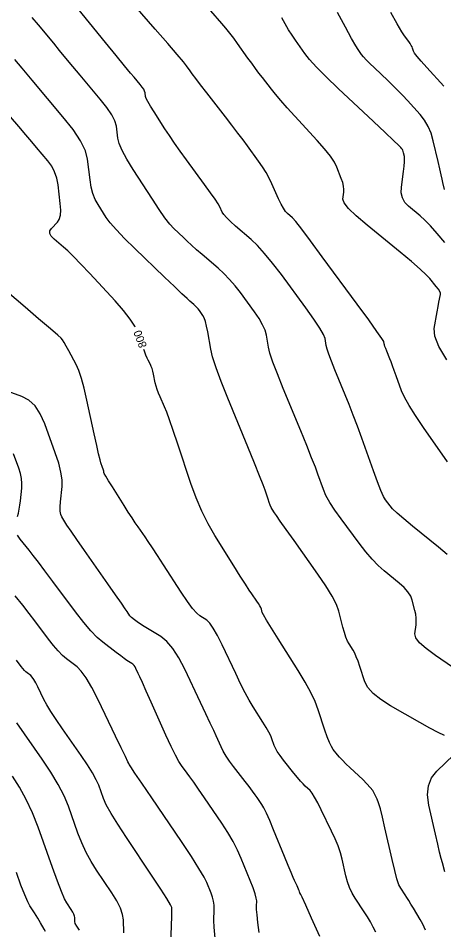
# Model space of a CAD drawing. Extents: x 2082232 to 2083549, y 592624 to 593832.
# Drawn here: x 2082448.2 to 2082485.4, y 593145.7 to 593225.4 of the extents above; entities that cross this region are included whole.
import ezdxf

# ---------------------------------------------------------------- set-up
doc = ezdxf.new("R2010")
doc.units = 0
doc.layers.add('DT_X_Contour_Major', color=7, linetype='Continuous')
doc.layers.add('DT_X_Contour_Minor', color=7, linetype='Continuous')

msp = doc.modelspace()

# ---------------------------------------------------------------- linework, layer by layer
at = {"layer": 'DT_X_Contour_Major'}
for points in [[(2082485.658, 593195.556), (2082484.97, 593196.729), (2082484.597, 593197.648), (2082484.539, 593198.314), (2082484.807, 593199.752), (2082484.898, 593200.235), (2082484.969, 593200.607), (2082485.021, 593200.868), (2082485.053, 593201.018), (2082485.113, 593201.268), (2082485.107, 593201.383), (2082485.042, 593201.539), (2082484.919, 593201.737), (2082484.738, 593201.976), (2082484.178, 593202.669), (2082483.859, 593203.008), (2082483.32, 593203.505), (2082482.563, 593204.16), (2082481.586, 593204.973), (2082478.69, 593207.352), (2082477.744, 593208.161), (2082477.076, 593208.805), (2082476.688, 593209.284), (2082476.579, 593209.597), (2082476.659, 593210.212), (2082476.668, 593210.461), (2082476.634, 593210.744), (2082476.556, 593211.064), (2082476.436, 593211.418), (2082476.056, 593212.411), (2082475.841, 593212.837), (2082475.479, 593213.367), (2082474.971, 593214.004), (2082474.316, 593214.745), (2082472.375, 593216.864), (2082471.702, 593217.607), (2082471.136, 593218.247), (2082470.678, 593218.784), (2082470.328, 593219.218), (2082469.54, 593220.237), (2082469.239, 593220.63), (2082468.928, 593221.046), (2082468.606, 593221.485), (2082468.275, 593221.946), (2082467.376, 593223.206), (2082467.036, 593223.671), (2082466.691, 593224.121), (2082466.342, 593224.556), (2082465.987, 593224.976), (2082465.033, 593226.075)], [(2082458.433, 593198.426), (2082458.396, 593198.504), (2082457.984, 593199.131), (2082457.404, 593199.867), (2082456.657, 593200.712), (2082454.443, 593203.112), (2082453.678, 593203.931), (2082453.043, 593204.59), (2082452.537, 593205.089), (2082452.162, 593205.427), (2082451.335, 593206.115), (2082451.088, 593206.367), (2082450.968, 593206.605), (2082450.973, 593206.831), (2082451.105, 593207.043), (2082451.625, 593207.591), (2082451.787, 593207.847), (2082451.882, 593208.205), (2082451.909, 593208.664), (2082451.87, 593209.224), (2082451.676, 593210.853), (2082451.566, 593211.442), (2082451.382, 593211.989), (2082451.124, 593212.492), (2082450.792, 593212.953), (2082449.808, 593214.125), (2082449.389, 593214.623), (2082448.871, 593215.238), (2082448.254, 593215.971), (2082447.537, 593216.821)], [(2082483.778, 593145.725), (2082483.551, 593146.237), (2082483.327, 593146.653), (2082482.733, 593147.639), (2082482.521, 593147.988), (2082482.329, 593148.299), (2082482.157, 593148.571), (2082482.005, 593148.803), (2082481.628, 593149.371), (2082481.475, 593149.688), (2082481.298, 593150.212), (2082481.098, 593150.943), (2082480.875, 593151.882), (2082480.249, 593154.662), (2082480.031, 593155.599), (2082479.847, 593156.327), (2082479.697, 593156.845), (2082479.581, 593157.154), (2082479.317, 593157.697), (2082479.179, 593157.924), (2082478.964, 593158.195), (2082478.671, 593158.512), (2082478.301, 593158.875), (2082477.211, 593159.902), (2082476.835, 593160.262), (2082476.525, 593160.57), (2082476.282, 593160.827), (2082476.104, 593161.033), (2082475.72, 593161.514), (2082475.566, 593161.754), (2082475.395, 593162.117), (2082475.205, 593162.6), (2082474.997, 593163.206), (2082474.417, 593164.981), (2082474.145, 593165.694), (2082473.761, 593166.502), (2082473.267, 593167.403), (2082472.662, 593168.4), (2082470.902, 593171.182), (2082470.321, 593172.109), (2082469.897, 593172.802), (2082469.632, 593173.263), (2082469.524, 593173.491), (2082469.448, 593173.787), (2082469.402, 593173.914), (2082469.322, 593174.072), (2082469.207, 593174.26), (2082469.057, 593174.48), (2082468.613, 593175.107), (2082468.389, 593175.436), (2082468.053, 593175.955), (2082467.604, 593176.663), (2082467.042, 593177.56), (2082465.392, 593180.203), (2082464.797, 593181.232), (2082464.249, 593182.335), (2082463.748, 593183.513), (2082463.294, 593184.766), (2082462.146, 593188.207), (2082461.751, 593189.378), (2082461.427, 593190.309), (2082461.173, 593191), (2082460.99, 593191.451), (2082460.597, 593192.336), (2082460.46, 593192.661), (2082460.345, 593192.974), (2082460.252, 593193.274), (2082460.181, 593193.561), (2082460.02, 593194.311), (2082459.958, 593194.574), (2082459.891, 593194.804), (2082459.822, 593194.998), (2082459.748, 593195.158), (2082459.546, 593195.539), (2082459.46, 593195.722), (2082459.352, 593195.985), (2082459.223, 593196.328), (2082459.175, 593196.463)], [(2082461.567, 593145.097), (2082461.603, 593146.311), (2082461.615, 593146.723), (2082461.622, 593147.045), (2082461.626, 593147.279), (2082461.625, 593147.425), (2082461.618, 593147.694), (2082461.51, 593147.941), (2082461.19, 593148.479), (2082460.66, 593149.308), (2082459.918, 593150.429), (2082457.658, 593153.804), (2082456.897, 593154.967), (2082456.308, 593155.922), (2082455.893, 593156.669), (2082455.65, 593157.21), (2082455.232, 593158.374), (2082455.019, 593158.865), (2082454.691, 593159.466), (2082454.25, 593160.176), (2082453.695, 593160.995), (2082452.062, 593163.324), (2082451.502, 593164.14), (2082451.045, 593164.838), (2082450.693, 593165.421), (2082450.444, 593165.886), (2082449.919, 593166.973), (2082449.732, 593167.34), (2082449.566, 593167.627), (2082449.42, 593167.835), (2082449.295, 593167.962), (2082448.987, 593168.194), (2082448.867, 593168.295), (2082448.738, 593168.425), (2082448.601, 593168.583), (2082448.455, 593168.77), (2082448.054, 593169.307)]]:
    msp.add_lwpolyline(points, dxfattribs=at)
at = {"layer": 'DT_X_Contour_Minor'}
for points in [[(2082485.711, 593186.655), (2082483.622, 593189.646), (2082482.914, 593190.688), (2082482.358, 593191.574), (2082481.955, 593192.301), (2082481.703, 593192.871), (2082481.235, 593194.181), (2082481.068, 593194.642), (2082480.92, 593195.043), (2082480.789, 593195.384), (2082480.678, 593195.664), (2082480.403, 593196.331), (2082480.312, 593196.558), (2082480.243, 593196.742), (2082480.197, 593196.88), (2082480.173, 593196.974), (2082480.141, 593197.164), (2082479.987, 593197.421), (2082479.55, 593198.051), (2082478.83, 593199.052), (2082477.827, 593200.426), (2082474.775, 593204.585), (2082473.754, 593205.967), (2082472.977, 593206.995), (2082472.446, 593207.668), (2082472.16, 593207.986), (2082471.724, 593208.361), (2082471.553, 593208.546), (2082471.369, 593208.821), (2082471.171, 593209.184), (2082470.958, 593209.636), (2082470.374, 593210.961), (2082470.137, 593211.458), (2082469.864, 593211.953), (2082469.555, 593212.448), (2082469.21, 593212.942), (2082468.243, 593214.259), (2082467.849, 593214.79), (2082467.395, 593215.393), (2082466.879, 593216.068), (2082466.303, 593216.817), (2082464.684, 593218.909), (2082464.137, 593219.617), (2082463.712, 593220.172), (2082463.409, 593220.572), (2082463.226, 593220.82), (2082462.902, 593221.274), (2082462.64, 593221.602), (2082462.099, 593222.246), (2082461.276, 593223.206), (2082460.174, 593224.481), (2082456.861, 593228.301)], [(2082485.688, 593178.55), (2082484.915, 593179.184), (2082482.666, 593181.036), (2082481.91, 593181.668), (2082481.328, 593182.175), (2082480.922, 593182.556), (2082480.69, 593182.812), (2082480.305, 593183.328), (2082480.13, 593183.631), (2082479.896, 593184.154), (2082479.602, 593184.896), (2082479.249, 593185.858), (2082478.227, 593188.716), (2082477.849, 593189.757), (2082477.482, 593190.736), (2082477.127, 593191.652), (2082476.783, 593192.507), (2082475.88, 593194.702), (2082475.578, 593195.452), (2082475.352, 593196.055), (2082475.199, 593196.51), (2082475.122, 593196.819), (2082475.015, 593197.445), (2082474.879, 593197.787), (2082474.554, 593198.343), (2082474.038, 593199.114), (2082473.331, 593200.099), (2082471.194, 593203.012), (2082470.429, 593204.023), (2082469.736, 593204.871), (2082469.115, 593205.556), (2082468.567, 593206.078), (2082467.202, 593207.254), (2082466.744, 593207.662), (2082466.396, 593208.002), (2082466.156, 593208.275), (2082466.025, 593208.481), (2082465.822, 593208.942), (2082465.682, 593209.193), (2082465.413, 593209.602), (2082465.016, 593210.169), (2082464.49, 593210.893), (2082462.917, 593213.035), (2082462.356, 593213.807), (2082461.853, 593214.518), (2082461.408, 593215.168), (2082461.021, 593215.756), (2082460.066, 593217.242), (2082459.752, 593217.745), (2082459.522, 593218.138), (2082459.379, 593218.422), (2082459.322, 593218.596), (2082459.284, 593218.916), (2082459.246, 593219.051), (2082459.163, 593219.215), (2082459.032, 593219.408), (2082458.856, 593219.631), (2082458.323, 593220.266), (2082458.017, 593220.635), (2082457.499, 593221.266), (2082456.769, 593222.16), (2082455.827, 593223.316), (2082453.031, 593226.749)], [(2082485.464, 593210.462), (2082485.311, 593211.066), (2082485.242, 593211.35), (2082485.148, 593211.749), (2082485.03, 593212.262), (2082484.888, 593212.89), (2082484.476, 593214.717), (2082484.288, 593215.374), (2082484.035, 593215.974), (2082483.717, 593216.517), (2082483.333, 593217.004), (2082482.222, 593218.226), (2082481.802, 593218.679), (2082481.376, 593219.121), (2082480.944, 593219.553), (2082480.505, 593219.975), (2082479.326, 593221.084), (2082478.925, 593221.469), (2082478.605, 593221.792), (2082478.367, 593222.052), (2082478.21, 593222.249), (2082477.9, 593222.693), (2082477.702, 593223.02), (2082477.338, 593223.669), (2082476.808, 593224.64), (2082476.114, 593225.933)], [(2082485.4, 593219.477), (2082483.912, 593221.114), (2082483.421, 593221.663), (2082483.061, 593222.084), (2082482.833, 593222.376), (2082482.737, 593222.54), (2082482.658, 593222.805), (2082482.615, 593222.916), (2082482.544, 593223.049), (2082482.447, 593223.205), (2082482.323, 593223.384), (2082481.956, 593223.892), (2082481.73, 593224.245), (2082481.327, 593224.924), (2082480.748, 593225.928)], [(2082487.178, 593167.998), (2082484.661, 593169.724), (2082483.84, 593170.327), (2082483.265, 593170.841), (2082482.937, 593171.268), (2082482.854, 593171.606), (2082482.963, 593172.389), (2082482.987, 593172.689), (2082482.98, 593173), (2082482.941, 593173.323), (2082482.87, 593173.657), (2082482.638, 593174.564), (2082482.5, 593174.912), (2082482.261, 593175.276), (2082481.921, 593175.657), (2082481.48, 593176.053), (2082480.17, 593177.133), (2082479.666, 593177.586), (2082479.135, 593178.138), (2082478.579, 593178.787), (2082477.997, 593179.534), (2082476.41, 593181.657), (2082475.867, 593182.416), (2082475.428, 593183.1), (2082475.094, 593183.708), (2082474.865, 593184.241), (2082474.392, 593185.564), (2082474.165, 593186.172), (2082473.839, 593187.006), (2082473.413, 593188.065), (2082472.888, 593189.349), (2082471.356, 593193.074), (2082470.845, 593194.345), (2082470.46, 593195.368), (2082470.202, 593196.141), (2082470.071, 593196.664), (2082469.889, 593197.726), (2082469.772, 593198.153), (2082469.557, 593198.636), (2082469.245, 593199.176), (2082468.836, 593199.773), (2082467.613, 593201.439), (2082467.147, 593202.041), (2082466.667, 593202.599), (2082466.172, 593203.111), (2082465.662, 593203.579), (2082464.284, 593204.766), (2082463.793, 593205.192), (2082463.353, 593205.583), (2082462.965, 593205.936), (2082462.629, 593206.254), (2082461.799, 593207.051), (2082461.449, 593207.434), (2082461.019, 593207.987), (2082460.51, 593208.71), (2082459.923, 593209.602), (2082458.249, 593212.208), (2082457.694, 593213.112), (2082457.284, 593213.871), (2082457.02, 593214.484), (2082456.9, 593214.952), (2082456.774, 593216.005), (2082456.651, 593216.449), (2082456.375, 593216.99), (2082455.945, 593217.628), (2082455.363, 593218.363), (2082453.607, 593220.454), (2082452.969, 593221.216), (2082452.372, 593221.934), (2082451.815, 593222.608), (2082451.3, 593223.237), (2082449.981, 593224.858), (2082449.431, 593225.482)], [(2082485.47, 593205.82), (2082484.814, 593206.612), (2082484.237, 593207.267), (2082483.74, 593207.785), (2082483.321, 593208.165), (2082482.311, 593208.994), (2082481.988, 593209.332), (2082481.776, 593209.721), (2082481.677, 593210.162), (2082481.689, 593210.655), (2082481.871, 593212.04), (2082481.927, 593212.51), (2082481.959, 593212.882), (2082481.967, 593213.157), (2082481.95, 593213.332), (2082481.874, 593213.671), (2082481.844, 593213.787), (2082481.811, 593213.883), (2082481.776, 593213.957), (2082481.738, 593214.011), (2082481.634, 593214.126), (2082481.455, 593214.3), (2082480.997, 593214.735), (2082480.259, 593215.432), (2082479.242, 593216.39), (2082476.158, 593219.294), (2082475.108, 593220.301), (2082474.271, 593221.145), (2082473.647, 593221.826), (2082473.237, 593222.342), (2082472.428, 593223.502), (2082472.126, 593223.951), (2082471.827, 593224.426), (2082471.532, 593224.929), (2082471.24, 593225.458)], [(2082485.463, 593162.727), (2082484.899, 593162.995), (2082484.177, 593163.376), (2082483.296, 593163.868), (2082480.737, 593165.332), (2082479.877, 593165.874), (2082479.216, 593166.404), (2082478.755, 593166.922), (2082478.492, 593167.427), (2082478.058, 593168.757), (2082477.899, 593169.22), (2082477.747, 593169.611), (2082477.603, 593169.93), (2082477.465, 593170.177), (2082477.109, 593170.74), (2082476.976, 593170.99), (2082476.842, 593171.317), (2082476.708, 593171.721), (2082476.575, 593172.202), (2082476.218, 593173.589), (2082476.004, 593174.181), (2082475.627, 593174.919), (2082475.089, 593175.802), (2082474.39, 593176.829), (2082472.308, 593179.763), (2082471.615, 593180.74), (2082471.099, 593181.473), (2082470.759, 593181.961), (2082470.596, 593182.204), (2082470.395, 593182.527), (2082470.316, 593182.671), (2082470.231, 593182.86), (2082470.139, 593183.096), (2082470.041, 593183.377), (2082469.77, 593184.188), (2082469.6, 593184.652), (2082469.292, 593185.438), (2082468.845, 593186.545), (2082468.261, 593187.973), (2082466.519, 593192.208), (2082465.935, 593193.668), (2082465.491, 593194.872), (2082465.185, 593195.819), (2082465.02, 593196.509), (2082464.763, 593198.007), (2082464.664, 593198.519), (2082464.561, 593198.929), (2082464.453, 593199.238), (2082464.34, 593199.446), (2082464.032, 593199.866), (2082463.914, 593200.018), (2082463.793, 593200.158), (2082463.669, 593200.287), (2082463.54, 593200.405), (2082463.193, 593200.704), (2082462.957, 593200.92), (2082462.51, 593201.341), (2082461.851, 593201.97), (2082460.981, 593202.804), (2082458.378, 593205.306), (2082457.491, 593206.179), (2082456.78, 593206.922), (2082456.247, 593207.535), (2082455.89, 593208.017), (2082455.174, 593209.131), (2082454.93, 593209.581), (2082454.732, 593210.093), (2082454.582, 593210.669), (2082454.478, 593211.307), (2082454.265, 593213.094), (2082454.07, 593213.83), (2082453.644, 593214.696), (2082452.988, 593215.693), (2082452.102, 593216.82), (2082449.431, 593219.999), (2082448.545, 593221.054), (2082447.892, 593221.832)], [(2082479.438, 593145.529), (2082479.225, 593145.98), (2082478.988, 593146.43), (2082478.728, 593146.877), (2082478.445, 593147.322), (2082477.659, 593148.505), (2082477.386, 593148.961), (2082477.156, 593149.441), (2082476.969, 593149.946), (2082476.825, 593150.474), (2082476.501, 593151.915), (2082476.352, 593152.474), (2082476.15, 593153.071), (2082475.894, 593153.707), (2082475.585, 593154.38), (2082474.688, 593156.226), (2082474.374, 593156.85), (2082474.105, 593157.339), (2082473.879, 593157.692), (2082473.699, 593157.909), (2082473.276, 593158.307), (2082473.095, 593158.491), (2082472.869, 593158.742), (2082472.598, 593159.062), (2082472.283, 593159.45), (2082471.382, 593160.576), (2082471.078, 593160.972), (2082470.84, 593161.317), (2082470.669, 593161.612), (2082470.564, 593161.855), (2082470.375, 593162.435), (2082470.273, 593162.689), (2082470.108, 593163.016), (2082469.88, 593163.415), (2082469.59, 593163.887), (2082468.733, 593165.242), (2082468.396, 593165.804), (2082468.029, 593166.474), (2082467.631, 593167.251), (2082467.203, 593168.137), (2082466.02, 593170.643), (2082465.603, 593171.483), (2082465.24, 593172.123), (2082464.931, 593172.563), (2082464.676, 593172.804), (2082464.068, 593173.179), (2082463.795, 593173.414), (2082463.436, 593173.838), (2082462.988, 593174.45), (2082462.452, 593175.251), (2082460.908, 593177.639), (2082460.372, 593178.463), (2082459.924, 593179.146), (2082459.563, 593179.687), (2082459.29, 593180.085), (2082458.678, 593180.96), (2082458.43, 593181.323), (2082458.143, 593181.757), (2082457.817, 593182.261), (2082457.453, 593182.834), (2082456.432, 593184.458), (2082456.097, 593184.995), (2082455.859, 593185.385), (2082455.717, 593185.63), (2082455.671, 593185.729), (2082455.679, 593185.8), (2082455.674, 593185.842), (2082455.655, 593185.915), (2082455.622, 593186.019), (2082455.574, 593186.155), (2082455.428, 593186.557), (2082455.351, 593186.829), (2082455.227, 593187.34), (2082455.057, 593188.093), (2082454.841, 593189.085), (2082454.203, 593192.053), (2082453.965, 593193.082), (2082453.726, 593193.946), (2082453.489, 593194.643), (2082453.251, 593195.173), (2082452.62, 593196.367), (2082452.4, 593196.771), (2082452.214, 593197.087), (2082452.061, 593197.315), (2082451.943, 593197.456), (2082451.673, 593197.714), (2082451.417, 593197.939), (2082450.854, 593198.422), (2082449.982, 593199.161), (2082448.803, 593200.158), (2082445.247, 593203.16)], [(2082474.543, 593145.17), (2082473.836, 593146.753), (2082473.325, 593147.893), (2082473.01, 593148.589), (2082472.891, 593148.842), (2082472.835, 593148.926), (2082472.816, 593148.958), (2082472.799, 593148.992), (2082472.786, 593149.028), (2082472.776, 593149.066), (2082472.753, 593149.168), (2082472.735, 593149.223), (2082472.698, 593149.312), (2082472.642, 593149.434), (2082472.568, 593149.59), (2082472.344, 593150.05), (2082472.226, 593150.311), (2082472.04, 593150.748), (2082471.786, 593151.362), (2082471.463, 593152.153), (2082470.511, 593154.497), (2082470.179, 593155.294), (2082469.9, 593155.927), (2082469.671, 593156.396), (2082469.495, 593156.701), (2082469.092, 593157.296), (2082468.913, 593157.552), (2082468.676, 593157.874), (2082468.383, 593158.263), (2082468.032, 593158.717), (2082467.02, 593160.017), (2082466.668, 593160.49), (2082466.369, 593160.933), (2082466.124, 593161.346), (2082465.932, 593161.728), (2082465.492, 593162.71), (2082465.284, 593163.168), (2082464.988, 593163.807), (2082464.604, 593164.626), (2082464.134, 593165.625), (2082462.762, 593168.531), (2082462.244, 593169.527), (2082461.719, 593170.333), (2082461.188, 593170.95), (2082460.65, 593171.379), (2082459.205, 593172.27), (2082458.721, 593172.579), (2082458.35, 593172.837), (2082458.093, 593173.046), (2082457.95, 593173.204), (2082457.72, 593173.559), (2082457.55, 593173.812), (2082457.211, 593174.302), (2082456.704, 593175.031), (2082456.029, 593175.998), (2082454.003, 593178.893), (2082453.325, 593179.864), (2082452.812, 593180.605), (2082452.462, 593181.115), (2082452.276, 593181.395), (2082452, 593181.835), (2082451.915, 593182.042), (2082451.87, 593182.334), (2082451.863, 593182.709), (2082451.895, 593183.169), (2082452.032, 593184.507), (2082452.034, 593185.065), (2082451.936, 593185.738), (2082451.738, 593186.525), (2082451.44, 593187.426), (2082450.514, 593189.979), (2082450.129, 593190.847), (2082449.667, 593191.536), (2082449.129, 593192.045), (2082448.514, 593192.374), (2082446.773, 593193.013)], [(2082448.149, 593181.885), (2082448.222, 593182.175), (2082448.287, 593182.5), (2082448.343, 593182.859), (2082448.389, 593183.253), (2082448.502, 593184.347), (2082448.517, 593184.765), (2082448.479, 593185.198), (2082448.389, 593185.645), (2082448.245, 593186.108), (2082447.791, 593187.36)], [(2082469.248, 593145.51), (2082469.146, 593146.381), (2082469.076, 593147.053), (2082469.035, 593147.527), (2082469.025, 593147.803), (2082469.039, 593148.272), (2082469.007, 593148.516), (2082468.901, 593148.895), (2082468.721, 593149.41), (2082468.466, 593150.061), (2082467.688, 593151.976), (2082467.362, 593152.709), (2082466.969, 593153.469), (2082466.508, 593154.259), (2082465.979, 593155.076), (2082464.479, 593157.293), (2082463.963, 593158.052), (2082463.54, 593158.663), (2082463.209, 593159.128), (2082462.972, 593159.447), (2082462.463, 593160.101), (2082462.236, 593160.451), (2082461.934, 593161.01), (2082461.559, 593161.78), (2082461.111, 593162.758), (2082459.816, 593165.648), (2082459.382, 593166.616), (2082459.049, 593167.355), (2082458.819, 593167.863), (2082458.691, 593168.14), (2082458.487, 593168.574), (2082458.406, 593168.724), (2082458.319, 593168.85), (2082458.225, 593168.951), (2082458.124, 593169.028), (2082457.845, 593169.2), (2082457.699, 593169.298), (2082457.469, 593169.463), (2082457.155, 593169.694), (2082456.758, 593169.992), (2082455.586, 593170.876), (2082455.108, 593171.29), (2082454.554, 593171.872), (2082453.922, 593172.62), (2082453.214, 593173.535), (2082451.224, 593176.198), (2082450.534, 593177.116), (2082449.958, 593177.876), (2082449.496, 593178.477), (2082449.147, 593178.919), (2082448.368, 593179.885), (2082448.122, 593180.237)], [(2082465.401, 593145.017), (2082465.319, 593145.985), (2082465.299, 593146.551), (2082465.328, 593147.529), (2082465.32, 593147.893), (2082465.274, 593148.252), (2082465.191, 593148.606), (2082465.069, 593148.955), (2082464.694, 593149.878), (2082464.449, 593150.361), (2082463.996, 593151.117), (2082463.334, 593152.147), (2082462.464, 593153.451), (2082459.866, 593157.291), (2082459.013, 593158.551), (2082458.403, 593159.452), (2082458.036, 593159.994), (2082457.912, 593160.176), (2082457.906, 593160.184), (2082457.903, 593160.189), (2082457.899, 593160.197), (2082457.893, 593160.209), (2082457.886, 593160.225), (2082457.866, 593160.271), (2082457.787, 593160.435), (2082457.567, 593160.891), (2082457.206, 593161.64), (2082456.703, 593162.681), (2082455.173, 593165.848), (2082454.628, 593166.919), (2082454.141, 593167.759), (2082453.71, 593168.366), (2082453.338, 593168.742), (2082452.42, 593169.434), (2082452.063, 593169.736), (2082451.679, 593170.123), (2082451.27, 593170.596), (2082450.835, 593171.153), (2082449.639, 593172.752), (2082449.152, 593173.394), (2082448.588, 593174.121), (2082447.946, 593174.933)], [(2082457.422, 593145.483), (2082457.392, 593146.626), (2082457.32, 593147.093), (2082457.127, 593147.64), (2082456.811, 593148.266), (2082456.374, 593148.97), (2082455.047, 593150.953), (2082454.572, 593151.714), (2082454.142, 593152.508), (2082453.759, 593153.336), (2082453.421, 593154.198), (2082452.581, 593156.541), (2082452.202, 593157.458), (2082451.693, 593158.452), (2082451.056, 593159.522), (2082450.29, 593160.669), (2082448.074, 593163.83)], [(2082485.491, 593150.81), (2082485.263, 593151.603), (2082485.161, 593151.982), (2082485.028, 593152.525), (2082484.862, 593153.232), (2082484.664, 593154.103), (2082484.092, 593156.643), (2082483.975, 593157.543), (2082484.051, 593158.338), (2082484.32, 593159.028), (2082484.783, 593159.614), (2082486.276, 593161.035)], [(2082453.546, 593145.713), (2082453.324, 593146.05), (2082453.19, 593146.303), (2082453.143, 593146.473), (2082453.134, 593146.813), (2082453.113, 593146.952), (2082453.055, 593147.115), (2082452.961, 593147.301), (2082452.831, 593147.511), (2082452.436, 593148.102), (2082452.247, 593148.461), (2082451.977, 593149.094), (2082451.625, 593150.003), (2082451.192, 593151.186), (2082449.93, 593154.708), (2082449.435, 593155.978), (2082448.899, 593157.146), (2082448.322, 593158.212), (2082447.702, 593159.176)], [(2082450.596, 593145.585), (2082450.459, 593145.809), (2082450.152, 593146.347), (2082450.032, 593146.553), (2082449.903, 593146.767), (2082449.765, 593146.989), (2082449.618, 593147.22), (2082449.215, 593147.848), (2082449.028, 593148.205), (2082448.77, 593148.807), (2082448.442, 593149.653), (2082448.043, 593150.743)]]:
    msp.add_lwpolyline(points, dxfattribs=at)

# ---------------------------------------------------------------- texts
at = {"layer": 'DT_X_Contour_Major'}
msp.add_text('800', height=0.7, rotation=110.69913, dxfattribs=at).set_placement((2082459.458, 593196.774))

doc.saveas('drawing.dxf')
